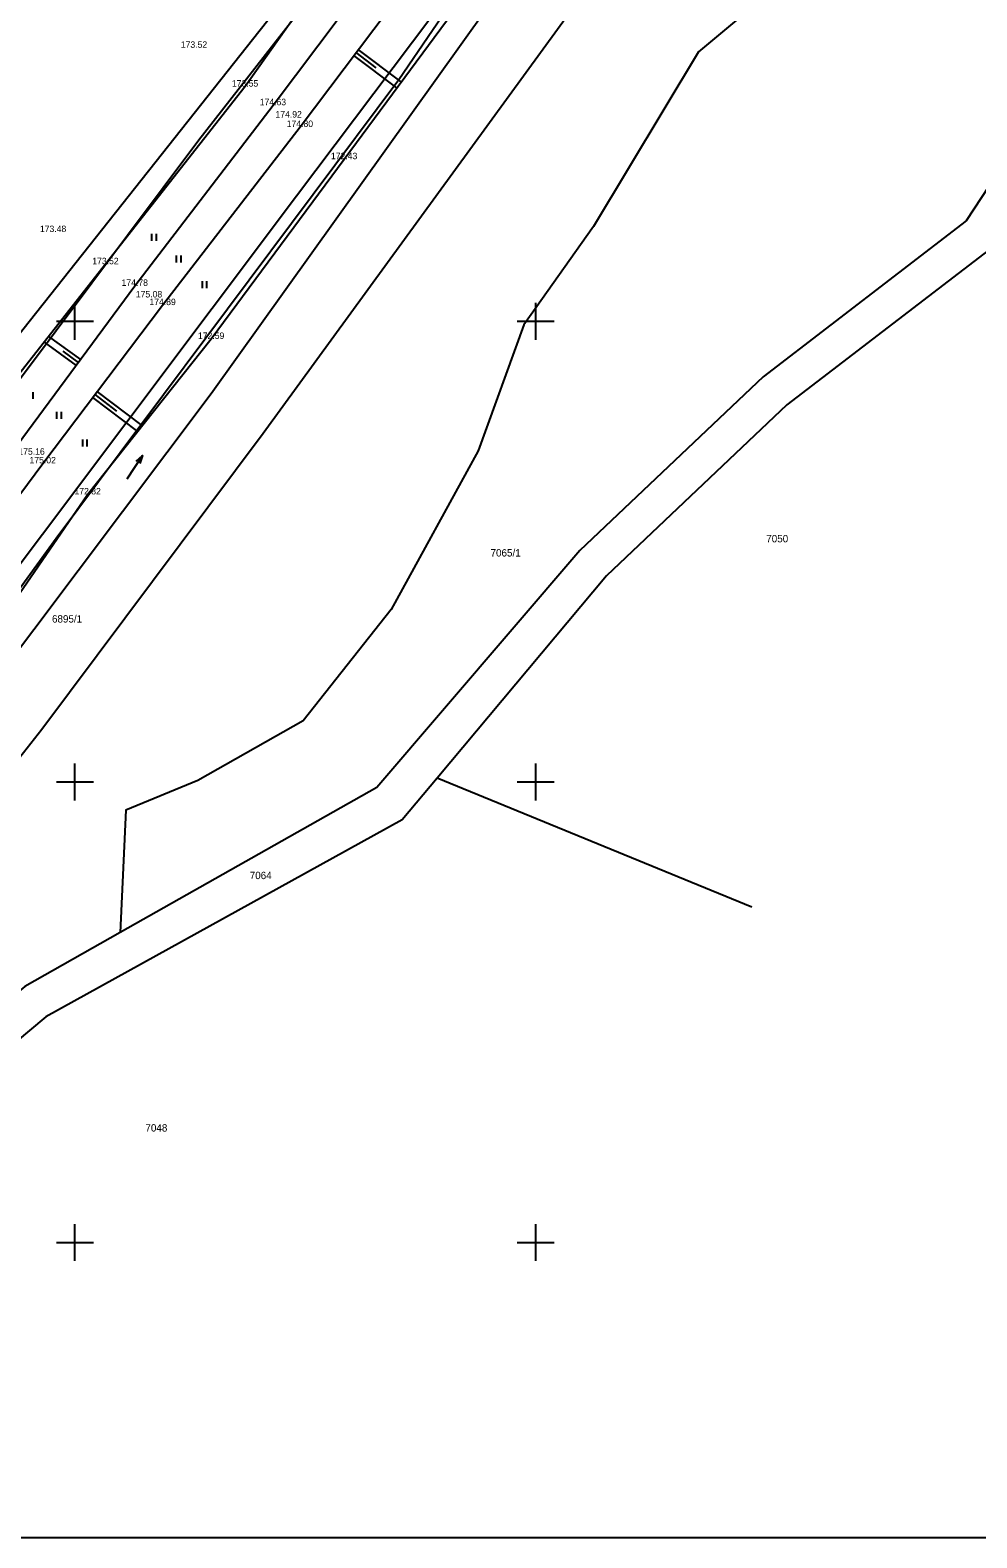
# Model space of a CAD drawing. Extents: x -612546 to -611926, y -1201932 to -1200444.
# Drawn here: x -612154.9 to -612052.1, y -1201932.1 to -1201768.4 of the extents above; entities that cross this region are included whole.
import ezdxf

# ---------------------------------------------------------------- set-up
doc = ezdxf.new("R2010")
doc.units = 0
for name, color, linetype in [('14 hrana pata svahu', 7, 'Continuous'), ('15 šrafy', 7, 'Continuous'), ('61 legenda křížky', 7, 'Continuous'), ('Hranice parcel', 7, 'Continuous'), ('Parcelní čísla', 7, 'Continuous'), ('Vnitřní kresba', 7, 'Continuous'), ('Vrstva 36', 7, 'Continuous'), ('Vrstva 45', 7, 'Continuous'), ('Vrstva 63', 7, 'Continuous'), ('výška bodu', 7, 'Continuous')]:
    doc.layers.add(name, color=color, linetype=linetype)

msp = doc.modelspace()

# ---------------------------------------------------------------- linework, layer by layer
at = {"layer": '14 hrana pata svahu'}
for points in [[(-612057.63, -1201582.88), (-612071.39, -1201603.6), (-612078.67, -1201621.43), (-612082.54, -1201641.2), (-612084.04, -1201663.45), (-612084.67, -1201687.81), (-612086.12, -1201697.99), (-612092.15, -1201712.3), (-612104.56, -1201734.15), (-612117.68, -1201754.92), (-612131.54, -1201774.52), (-612146.69, -1201793.8), (-612160.09, -1201810.84), (-612170.67, -1201824.21), (-612178.79, -1201837.39), (-612188.62, -1201833.24)], [(-612188.62, -1201833.24), (-612178.38, -1201842.08), (-612166.95, -1201827.44), (-612156.25, -1201813.45), (-612143.51, -1201796.15), (-612128.5, -1201776.54), (-612114.05, -1201757.31), (-612100.78, -1201736.11), (-612088.59, -1201713.94), (-612081.61, -1201699.59), (-612079.83, -1201687.94), (-612079.69, -1201663.54), (-612078, -1201641.59), (-612074.18, -1201622.35), (-612067.33, -1201605.71), (-612054.19, -1201585.24)], [(-612175.88, -1201845.11), (-612164.34, -1201830.03), (-612153.47, -1201815.42), (-612140.49, -1201798.24), (-612125.56, -1201778.9), (-612111.14, -1201759.71), (-612098.11, -1201738.16), (-612085.91, -1201715.6), (-612078.62, -1201701.15), (-612076.17, -1201688), (-612076, -1201663.36), (-612074.42, -1201641.97), (-612070.66, -1201623.2), (-612064.14, -1201607.91), (-612050.9, -1201587.38)], [(-612170.22, -1201849.2), (-612158.9, -1201833.69), (-612148.62, -1201818.79), (-612135.22, -1201801.91), (-612120.79, -1201782.4), (-612106.4, -1201762.88), (-612092.94, -1201741.41), (-612079.72, -1201718.14), (-612072.11, -1201703.96), (-612069.66, -1201687.98), (-612069.17, -1201663.58), (-612068.66, -1201643.17), (-612064.59, -1201625.96), (-612058.46, -1201609.91), (-612045.84, -1201591.45)]]:
    msp.add_lwpolyline(points, dxfattribs=at)
at = {"layer": '15 šrafy'}
for p, q in [((-612115.07, -1201774.65), (-612119.73, -1201771.14)), ((-612117.3, -1201772.47), (-612119.49, -1201770.82)), ((-612114.6, -1201774), (-612119.25, -1201770.5)), ((-612153.34, -1201802.26), (-612149.88, -1201804.81)), ((-612152.85, -1201801.63), (-612149.41, -1201804.16)), ((-612151.33, -1201803.24), (-612149.65, -1201804.48)), ((-612143.19, -1201811.95), (-612148.07, -1201808.27)), ((-612145.45, -1201809.74), (-612147.82, -1201807.95)), ((-612142.69, -1201811.32), (-612147.58, -1201807.63))]:
    msp.add_line(p, q, dxfattribs=at)
at = {"layer": '61 legenda křížky'}
for p, q in [((-612150, -1201802), (-612150, -1201798)), ((-612100, -1201802), (-612100, -1201798)), ((-612152, -1201800), (-612148, -1201800)), ((-612102, -1201800), (-612098, -1201800)), ((-612150, -1201852), (-612150, -1201848)), ((-612100, -1201852), (-612100, -1201848)), ((-612152, -1201850), (-612148, -1201850)), ((-612102, -1201850), (-612098, -1201850)), ((-612150, -1201902), (-612150, -1201898)), ((-612100, -1201902), (-612100, -1201898)), ((-612152, -1201900), (-612148, -1201900)), ((-612102, -1201900), (-612098, -1201900))]:
    msp.add_line(p, q, dxfattribs=at)
at = {"layer": 'Hranice parcel'}
msp.add_line((-612076.53, -1201863.61), (-612110.68, -1201849.58), dxfattribs=at)
for points in [[(-612177.46, -1201854.09), (-612171.97, -1201847.65), (-612125.97, -1201786.38), (-612109.19, -1201764.04), (-612092.57, -1201737.14), (-612080.39, -1201714.9), (-612074.78, -1201703.41), (-612071.98, -1201691.65), (-612072.2, -1201658.35), (-612070, -1201637.27), (-612065.73, -1201619.85), (-612059.82, -1201607.37), (-612039.46, -1201577.1), (-612017, -1201547.24), (-612004.68, -1201526.81), (-611998.92, -1201511.99), (-611996.24, -1201493.62), (-611996.58, -1201479.8), (-612000.74, -1201455.02), (-612027.1, -1201355.18), (-612050.25, -1201267.11)], [(-612060.22, -1201274.37), (-612037.81, -1201356.84), (-612011.62, -1201457.28), (-612007.48, -1201483.41), (-612008.37, -1201502.54), (-612012.46, -1201517.21), (-612025.5, -1201540.7), (-612047.75, -1201570.04), (-612070.24, -1201601.65), (-612078.31, -1201621), (-612081.97, -1201637.65), (-612083.96, -1201662.29), (-612084.12, -1201685.12), (-612084.75, -1201695.31), (-612087.47, -1201703.35), (-612103.05, -1201731.95), (-612118.98, -1201757.79), (-612136.57, -1201780.34), (-612179.16, -1201837.25), (-612189.22, -1201833.81)], [(-612058.05, -1201640.39), (-612059.55, -1201656.68), (-612059.01, -1201688.21), (-612061.34, -1201705.25), (-612076.22, -1201734.13), (-612093.67, -1201762.82), (-612129.56, -1201812.16), (-612153.59, -1201844.29), (-612161.99, -1201854.93), (-612167.05, -1201861.67), (-612182.62, -1201885.13)], [(-612058.05, -1201640.39), (-612052.46, -1201685.78), (-612053.25, -1201705.28), (-612052.26, -1201724.13), (-612061.14, -1201753.05), (-612082.33, -1201770.75), (-612093.73, -1201789.71), (-612101.27, -1201800.38), (-612106.23, -1201814.07), (-612115.7, -1201831.27), (-612125.23, -1201843.35), (-612136.68, -1201849.84), (-612144.46, -1201853.06), (-612145.1, -1201866.35)], [(-612045.15, -1201648.68), (-612044.76, -1201663.61), (-612042.82, -1201674.04), (-612039.6, -1201687.2), (-612038.01, -1201698.76), (-612033.05, -1201721.61), (-612029.71, -1201735.02), (-612029.19, -1201742.16), (-612031.22, -1201753.01), (-612038.64, -1201765.87), (-612042.48, -1201772.61), (-612053.27, -1201789.08), (-612075.33, -1201806.02), (-612095.2, -1201824.86), (-612117.25, -1201850.61), (-612145.1, -1201866.35)], [(-612189.22, -1201833.81), (-612176.37, -1201823.43), (-612164.9, -1201812.54), (-612126.3, -1201763.8), (-612120.3, -1201754.59)], [(-612039.07, -1201774.7), (-612050.3, -1201791.84), (-612072.73, -1201809.07), (-612092.3, -1201827.62), (-612110.68, -1201849.58)], [(-612110.68, -1201849.58), (-612114.49, -1201854.13), (-612153.17, -1201875.5), (-612171.18, -1201890.54), (-612171.46, -1201896.65)], [(-612145.1, -1201866.35), (-612155.45, -1201872.2), (-612173.83, -1201887.55), (-612180.83, -1201886.98)]]:
    msp.add_lwpolyline(points, dxfattribs=at)
at = {"layer": 'Vnitřní kresba'}
for points in [[(-612170.38, -1201848.81), (-612152.03, -1201823.55), (-612114.84, -1201773.75), (-612096.57, -1201746.92), (-612078.95, -1201716.04), (-612070.37, -1201697.01), (-612068.25, -1201638.15), (-612062.56, -1201619.7), (-612053.03, -1201601.55), (-612018.56, -1201552.89), (-611999.85, -1201519.56), (-611995.35, -1201499.82), (-611993.63, -1201480.57), (-612000.19, -1201450.02), (-612024.45, -1201357.81), (-612050.25, -1201267.11)], [(-612167.45, -1201850.95), (-612159.31, -1201839.87), (-612135.2, -1201807.83), (-612099.97, -1201758.55), (-612082.71, -1201730.21), (-612068.43, -1201702.85), (-612066.16, -1201687.46), (-612066.16, -1201656.85), (-612064.63, -1201639.3), (-612057.32, -1201615.06), (-612036.83, -1201583.77), (-612007.13, -1201540.95), (-611995.21, -1201517.05), (-611990.85, -1201487.68), (-611992.18, -1201466.53), (-612005.11, -1201415.22), (-612025.88, -1201339.7), (-612042.61, -1201277.13), (-612043.67, -1201266.17)]]:
    msp.add_lwpolyline(points, dxfattribs=at)
at = {"layer": 'Vrstva 36'}
for p, q in [((-612141.65, -1201791.26), (-612141.65, -1201790.51)), ((-612141.15, -1201791.26), (-612141.15, -1201790.51)), ((-612138.96, -1201793.61), (-612138.96, -1201792.86)), ((-612138.46, -1201793.61), (-612138.46, -1201792.86)), ((-612136.17, -1201796.4), (-612136.17, -1201795.65)), ((-612135.67, -1201796.4), (-612135.67, -1201795.65)), ((-612154.52, -1201808.43), (-612154.52, -1201807.68)), ((-612151.95, -1201810.59), (-612151.95, -1201809.84)), ((-612151.45, -1201810.59), (-612151.45, -1201809.84)), ((-612149.16, -1201813.57), (-612149.16, -1201812.82)), ((-612148.66, -1201813.57), (-612148.66, -1201812.82))]:
    msp.add_line(p, q, dxfattribs=at)
at = {"layer": 'Vrstva 45'}
msp.add_line((-612144.32, -1201817.09), (-612142.68, -1201814.58), dxfattribs=at)
msp.add_lwpolyline([(-612143.35, -1201815.18), (-612142.68, -1201814.58), (-612142.97, -1201815.43)], dxfattribs=at)
at = {"layer": 'Vrstva 63'}
msp.add_line((-611947.2, -1201932.06), (-612244.2, -1201932.06), dxfattribs=at)

# ---------------------------------------------------------------- texts
at = {"layer": 'Parcelní čísla'}
for s, p in [('7050', (-612074.98, -1201823.99)), ('7065/1', (-612104.9, -1201825.53)), ('6895/1', (-612152.49, -1201832.7)), ('7064', (-612131.03, -1201860.55)), ('7048', (-612142.35, -1201887.95))]:
    msp.add_text(s, height=0.8, dxfattribs=at).set_placement(p)
at = {"layer": 'výška bodu'}
for s, p in [('173.52', (-612138.51, -1201770.31)), ('173.55', (-612132.97, -1201774.52)), ('174.63', (-612129.95, -1201776.54)), ('174.92', (-612128.24, -1201777.88)), ('174.80', (-612127.02, -1201778.9)), ('172.43', (-612122.22, -1201782.4)), ('173.48', (-612153.8, -1201790.31)), ('173.52', (-612148.12, -1201793.8)), ('174.78', (-612144.94, -1201796.15)), ('175.08', (-612143.39, -1201797.41)), ('174.89', (-612141.92, -1201798.24)), ('172.59', (-612136.65, -1201801.91)), ('175.16', (-612156.14, -1201814.48)), ('175.02', (-612154.93, -1201815.42)), ('172.82', (-612150.05, -1201818.79))]:
    msp.add_text(s, height=0.7, dxfattribs=at).set_placement(p)

doc.saveas('drawing.dxf')
